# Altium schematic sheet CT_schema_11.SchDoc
size 742 x 377 mm
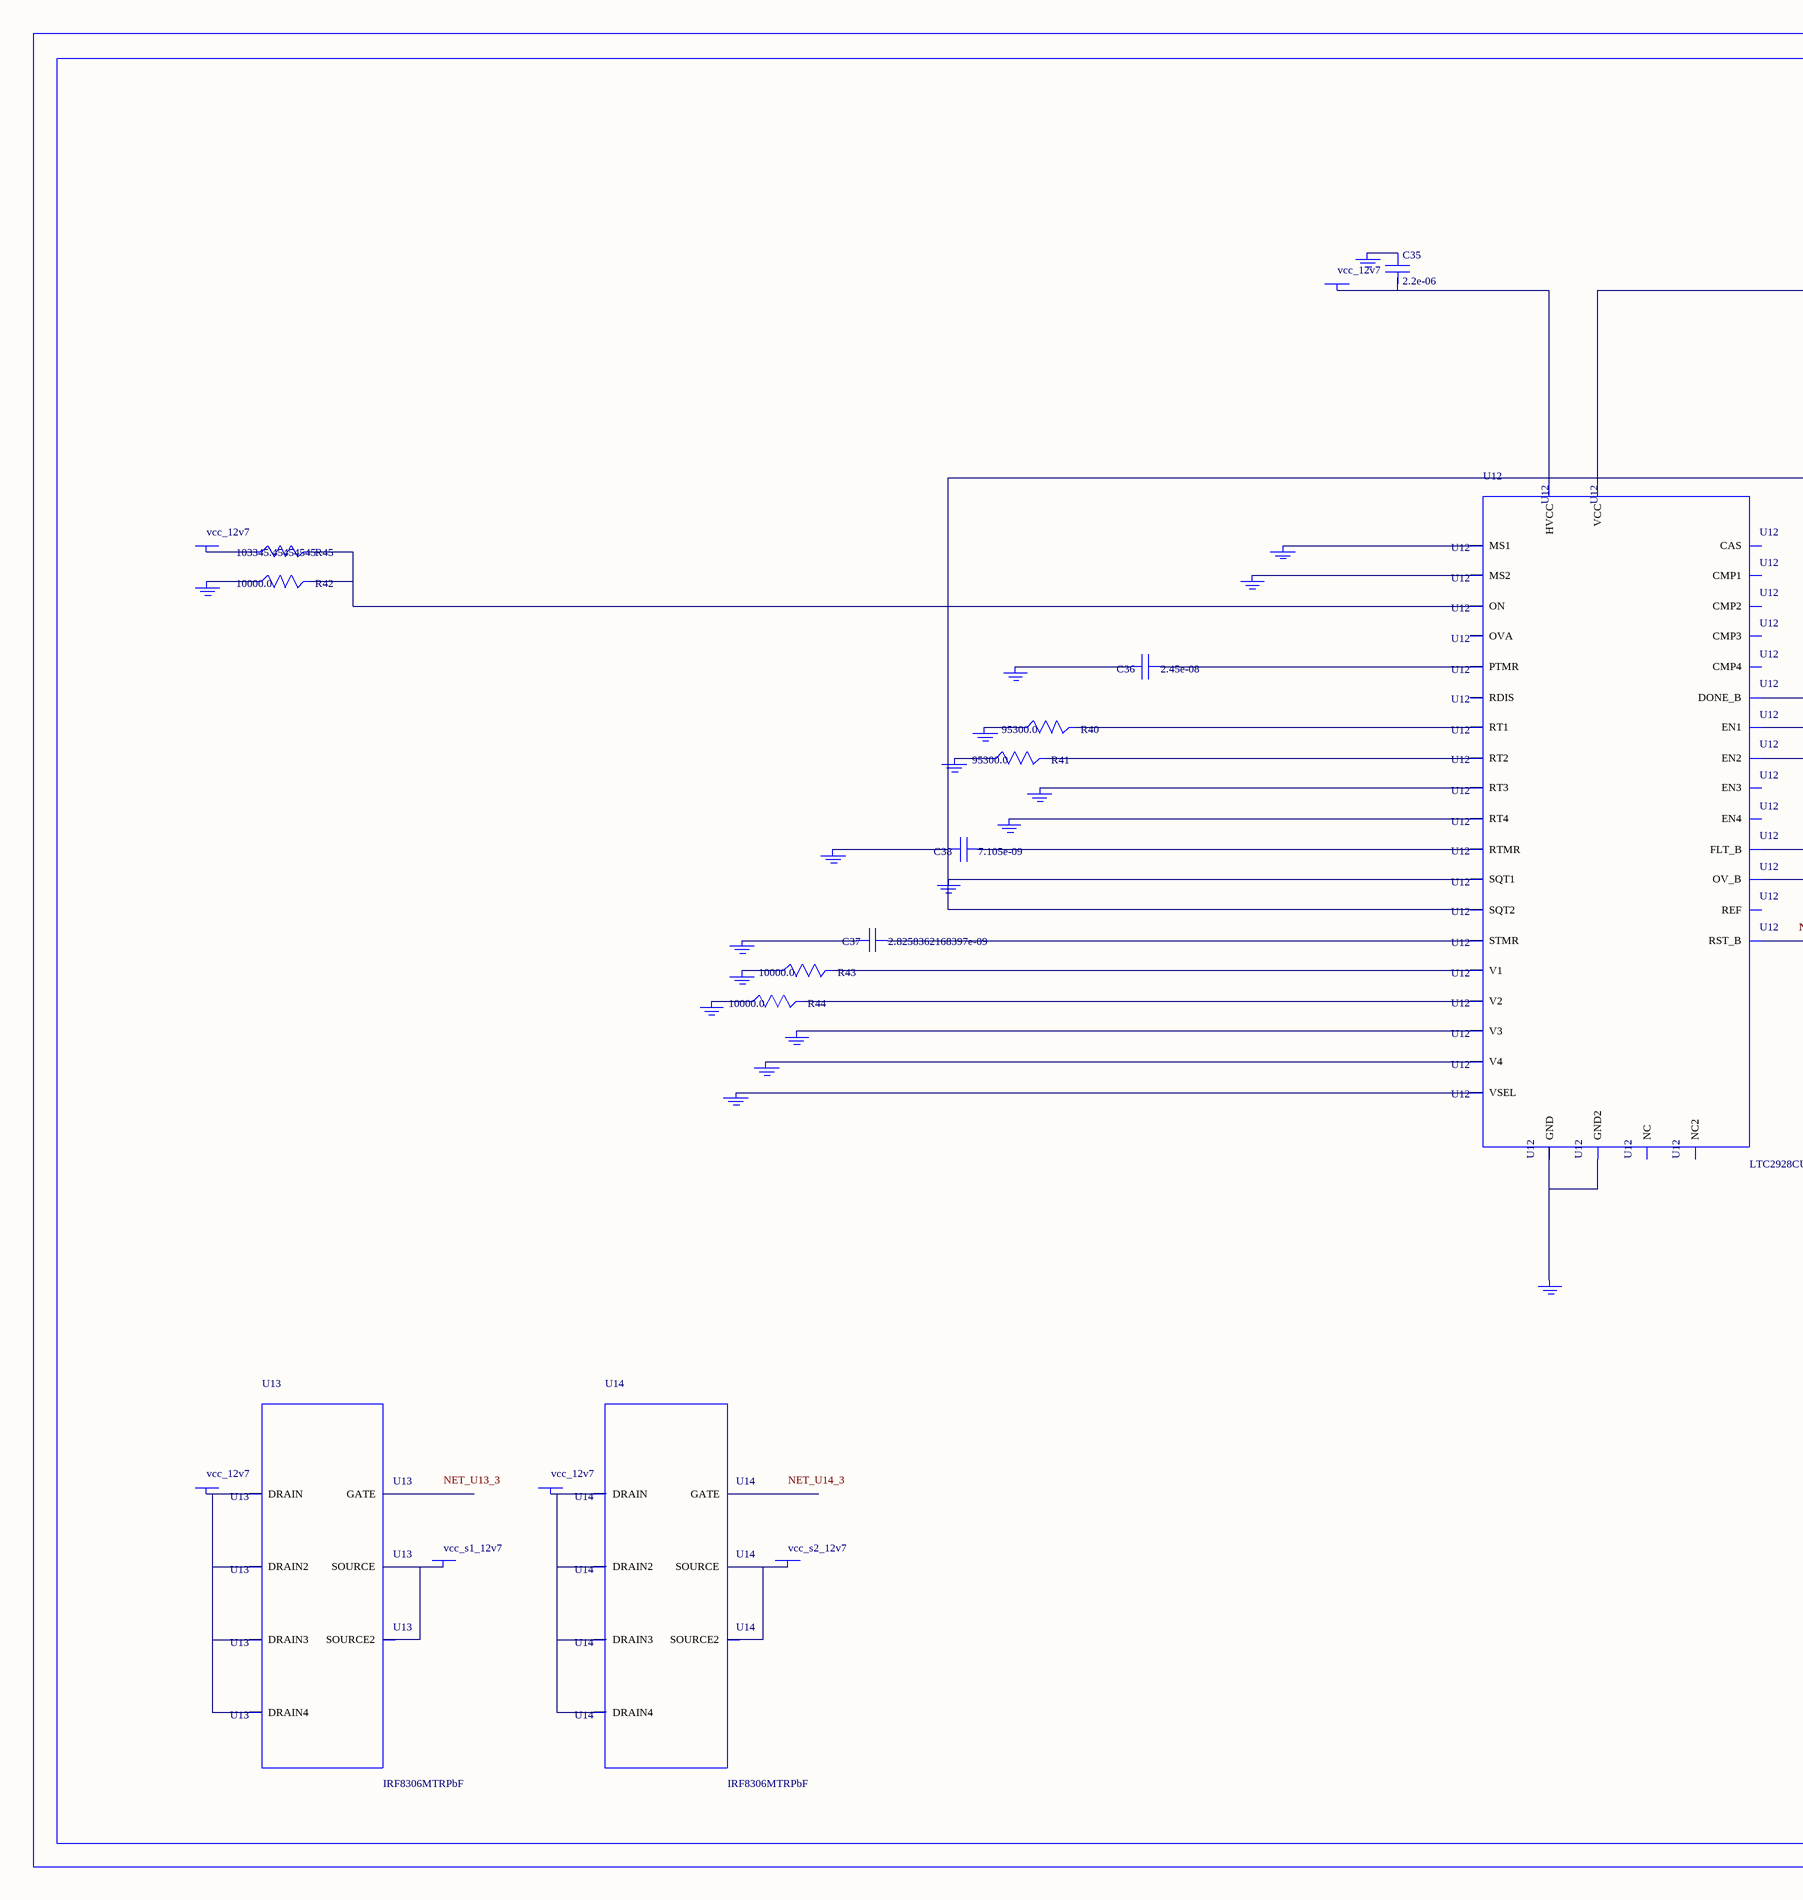
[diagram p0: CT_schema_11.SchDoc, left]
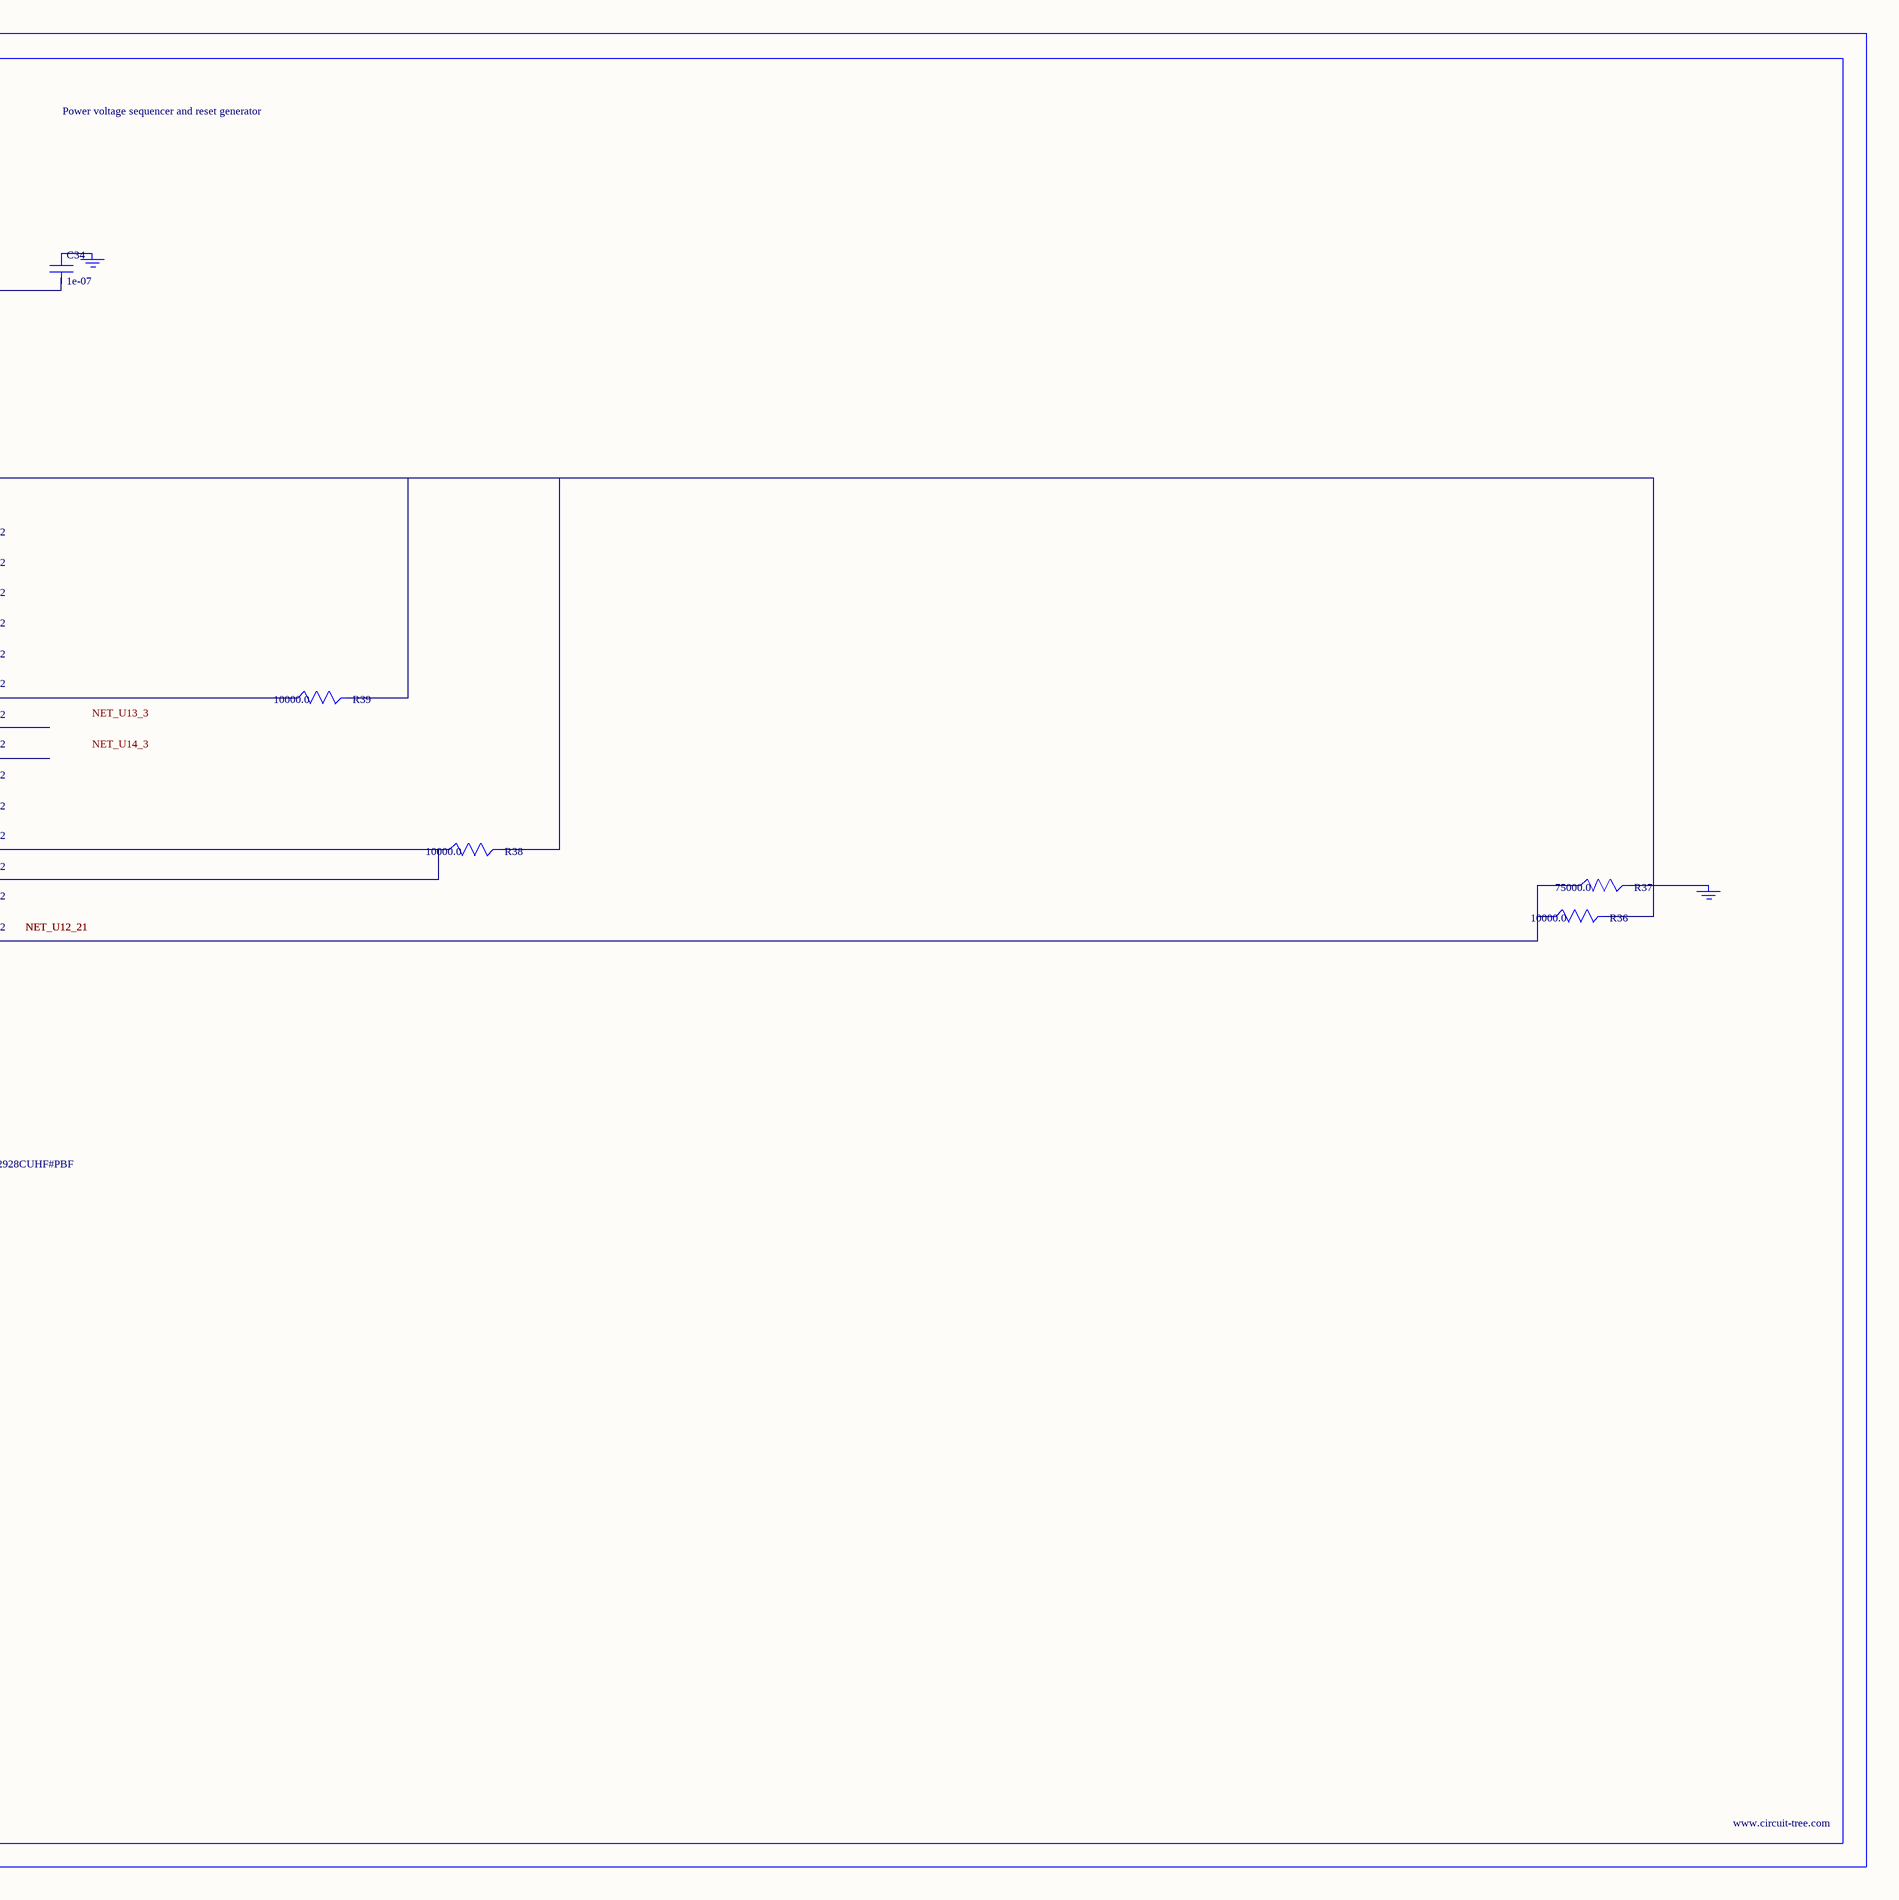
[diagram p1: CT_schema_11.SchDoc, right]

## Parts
BORDER10  (no value)
C34  1e-07  [C0402]
C35  2.2e-06  [C0603]
C36  2.45e-08  [R0603]
C37  2.8258362168397e-09  [R0603]
C38  7.105e-09  [R0603]
GND_INSTANCE_10_0  (no value)
GND_INSTANCE_10_1  (no value)
GND_INSTANCE_10_2  (no value)
GND_INSTANCE_10_3  (no value)
GND_INSTANCE_10_4  (no value)
GND_INSTANCE_10_5  (no value)
GND_INSTANCE_10_6  (no value)
GND_INSTANCE_10_7  (no value)
GND_INSTANCE_10_8  (no value)
GND_INSTANCE_10_9  (no value)
GND_INSTANCE_10_10  (no value)
GND_INSTANCE_10_11  (no value)
GND_INSTANCE_10_12  (no value)
GND_INSTANCE_10_13  (no value)
GND_INSTANCE_10_14  (no value)
GND_INSTANCE_10_15  (no value)
GND_INSTANCE_10_16  (no value)
GND_INSTANCE_10_17  (no value)
GND_INSTANCE_10_18  (no value)
GND_INSTANCE_10_19  (no value)
POWER_INSTANCE_10_0  vcc_12v7
POWER_INSTANCE_10_1  vcc_12v7
POWER_INSTANCE_10_2  vcc_12v7
POWER_INSTANCE_10_3  vcc_s1_12v7
POWER_INSTANCE_10_4  vcc_12v7
POWER_INSTANCE_10_5  vcc_s2_12v7
R36  10000.0  [R0603]
R37  75000.0  [R0603]
R38  10000.0  [R0603]
R39  10000.0  [R0603]
R40  95300.0  [R0603]
R41  95300.0  [R0603]
R42  10000.0  [R0603]
R43  10000.0  [R0603]
R44  10000.0  [R0603]
R45  103345.45454545  [R0603]
U12  LTC2928CUHF#PBF  [QFN-38_UHF]
U13  IRF8306MTRPbF  [IRF8306MTRPBF]
U14  IRF8306MTRPbF  [IRF8306MTRPBF]

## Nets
NetC34_1: C34.1 GND_INSTANCE_10_10.0(GND)
NetC34_2: C34.2 C38.2 GND_INSTANCE_10_5.0(GND) GND_INSTANCE_10_15.0(GND) R36.2 R38.2 R39.2 U12.10(SQT1) U12.11(SQT2) U12.22(VCC)
NetC35_1: C35.1 GND_INSTANCE_10_11.0(GND)
NetC35_2: C35.2 POWER_INSTANCE_10_1.0(PWR) U12.23(HVCC)
NetC36_1: C36.1 U12.27(PTMR)
NetC36_2: C36.2 GND_INSTANCE_10_14.0(GND)
NetC37_1: C37.1 U12.26(STMR)
NetC37_2: C37.2 GND_INSTANCE_10_13.0(GND)
NetC38_1: C38.1 U12.28(RTMR)
NetGND_INSTANCE_10_0_0: GND_INSTANCE_10_0.0(GND) R43.1
NetGND_INSTANCE_10_1_0: GND_INSTANCE_10_1.0(GND) R40.1
NetGND_INSTANCE_10_2_0: GND_INSTANCE_10_2.0(GND) R41.1
NetGND_INSTANCE_10_3_0: GND_INSTANCE_10_3.0(GND) U12.8(RT3)
NetGND_INSTANCE_10_4_0: GND_INSTANCE_10_4.0(GND) U12.9(RT4)
NetGND_INSTANCE_10_6_0: GND_INSTANCE_10_6.0(GND) U12.12(MS1)
NetGND_INSTANCE_10_7_0: GND_INSTANCE_10_7.0(GND) U12.13(MS2)
NetGND_INSTANCE_10_8_0: GND_INSTANCE_10_8.0(GND) R42.1
NetGND_INSTANCE_10_9_0: GND_INSTANCE_10_9.0(GND) R37.2
NetGND_INSTANCE_10_12_0: GND_INSTANCE_10_12.0(GND) U12.25(VSEL)
NetGND_INSTANCE_10_16_0: GND_INSTANCE_10_16.0(GND) U12.30(V4)
NetGND_INSTANCE_10_17_0: GND_INSTANCE_10_17.0(GND) U12.32(V3)
NetGND_INSTANCE_10_18_0: GND_INSTANCE_10_18.0(GND) R44.1
NetGND_INSTANCE_10_19_0: GND_INSTANCE_10_19.0(GND) U12.24(GND) U12.39(GND2)
NetPOWER_INSTANCE_10_0_0: POWER_INSTANCE_10_0.0(PWR) R45.1
NetPOWER_INSTANCE_10_2_0: POWER_INSTANCE_10_2.0(PWR) U13.1(DRAIN) U13.2(DRAIN2) U13.6(DRAIN3) U13.7(DRAIN4)
NetPOWER_INSTANCE_10_3_0: POWER_INSTANCE_10_3.0(PWR) U13.4(SOURCE) U13.5(SOURCE2)
NetPOWER_INSTANCE_10_4_0: POWER_INSTANCE_10_4.0(PWR) U14.1(DRAIN) U14.2(DRAIN2) U14.6(DRAIN3) U14.7(DRAIN4)
NetPOWER_INSTANCE_10_5_0: POWER_INSTANCE_10_5.0(PWR) U14.4(SOURCE) U14.5(SOURCE2)
NetR36_1: R36.1 R37.1 U12.21(RST_B)
NetR38_1: R38.1 U12.19(FLT_B) U12.20(OV_B)
NetR39_1: R39.1 U12.18(DONE_B)
NetR40_2: R40.2 U12.6(RT1)
NetR41_2: R41.2 U12.7(RT2)
NetR42_2: R42.2 R45.2 U12.16(ON)
NetR43_2: R43.2 U12.3(V1)
NetR44_2: R44.2 U12.38(V2)

Not connected (* = marked no-connect by the designer): U12 1(OVA) 2(EN1) 4(NC) 5(REF) 14(RDIS) 15(CAS) 17(NC2) 29(EN4) 31(EN3) 33(CMP3) 34(CMP4) 35(CMP1) 36(CMP2) 37(EN2); U13 3(GATE); U14 3(GATE)

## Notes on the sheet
- Labels drawn without touching a wire or pin: NET_U13_3, NET_U14_3

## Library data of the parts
BORDER10 = BORDER_PAGE10
C34 = C0402C104K3RACTU
C35 = GRM188R61H225KE1115D
C36 = C36
C37 = C37
C38 = C38
GND_INSTANCE_10_0-GND_INSTANCE_10_19 = GND
POWER_INSTANCE_10_0-POWER_INSTANCE_10_5 = PWR
R36 R38 R39 R42-R44 = RC0603JR-0710KL
R37 = RC0603JR-0775KL
R40 R41 = RC0603FR-0795K3L
R45 = R45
